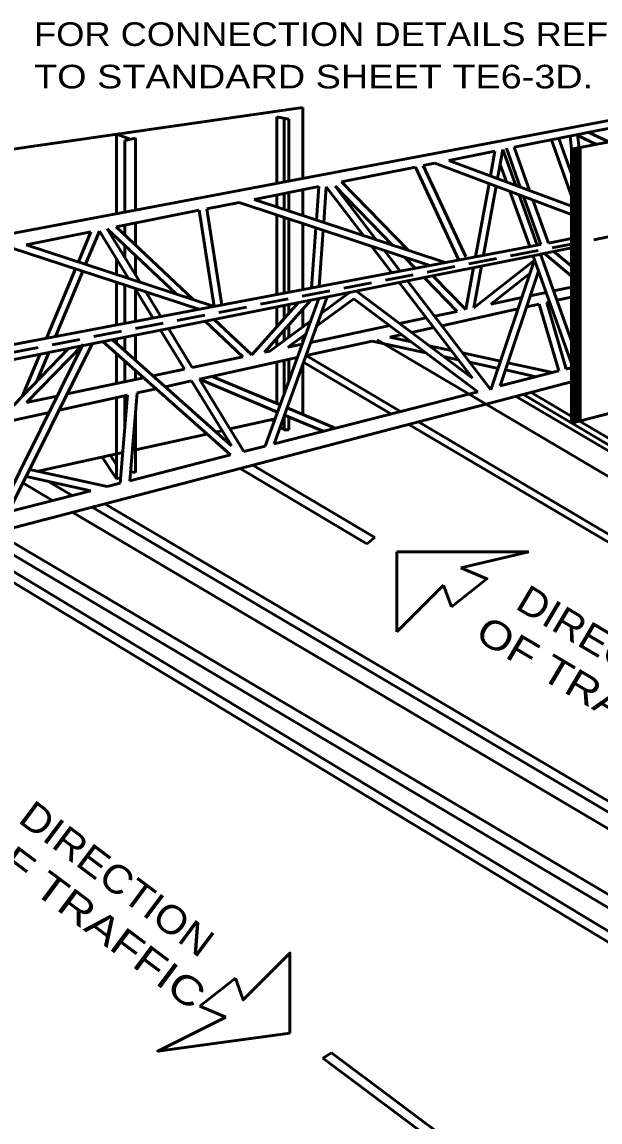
# Model space of a CAD drawing. Extents: x -111 to 744, y -77 to 467.
# Drawn here: x 499.2 to 572.7, y 204.3 to 344.2 of the extents above; entities that cross this region are included whole.
import ezdxf
from ezdxf.enums import TextEntityAlignment as Align

# ---------------------------------------------------------------- set-up
doc = ezdxf.new("R2010")
doc.units = 0
doc.header["$LTSCALE"] = 1.2
doc.linetypes.add('MEDIUM_DASHED', pattern=[4.5, 3, -1.5])
doc.layers.add('1', color=7, linetype='Continuous', lineweight=53)

msp = doc.modelspace()

# ---------------------------------------------------------------- linework, layer by layer
at = {"layer": '1'}
for p, q in [((561.783, 328.297), (612.161, 338.374)), ((569.111, 328.042), (604.991, 335.219)), ((483.311, 325.975), (534.911, 333.348)), ((534.911, 333.348), (534.911, 324.348)), ((531.611, 332.191), (531.611, 323.723)), ((531.611, 332.191), (533.111, 331.891)), ((532.511, 331.891), (532.511, 323.894)), ((533.111, 331.891), (533.111, 324.007)), ((511.211, 329.962), (512.936, 329.32)), ((511.211, 329.962), (511.211, 319.859)), ((512.261, 329.162), (513.611, 329.477)), ((512.261, 329.162), (512.261, 320.058)), ((513.611, 329.477), (513.611, 320.314)), ((566.541, 329.249), (569.111, 322.084)), ((567.493, 329.439), (569.111, 324.927)), ((569.111, 328.042), (568.92, 329.725)), ((569.709, 329.882), (572.27, 328.673)), ((570.065, 328.15), (569.865, 329.913)), ((571.288, 330.198), (573.849, 328.989)), ((553.471, 326.634), (559.354, 327.811)), ((559.354, 327.811), (558.775, 324.654)), ((560.367, 328.013), (559.688, 324.313)), ((560.367, 328.013), (562.005, 323.448)), ((560.808, 328.172), (562.579, 323.233)), ((561.783, 328.297), (563.757, 322.794)), ((569.111, 328.042), (569.111, 293.191)), ((569.399, 328.099), (569.399, 293.473)), ((569.607, 328.141), (569.607, 293.32)), ((569.815, 328.182), (569.815, 293.473)), ((570.023, 328.224), (570.023, 293.473)), ((570.191, 328.258), (570.191, 293.473)), ((550.213, 325.982), (551.683, 326.276)), ((551.683, 326.276), (569.111, 319.77)), ((553.471, 326.634), (569.111, 320.795)), ((560.022, 326.132), (560.827, 323.887)), ((569.191, 326.158), (569.191, 293.212)), ((569.503, 326.158), (569.503, 293.293)), ((539.831, 323.905), (549.244, 325.788)), ((549.244, 325.788), (554.764, 313.963)), ((550.213, 325.982), (555.634, 314.369)), ((528.697, 321.678), (536.933, 323.326)), ((536.933, 323.326), (536.631, 319.05)), ((537.891, 323.258), (537.572, 318.738)), ((537.891, 323.258), (542.624, 317.064)), ((539.02, 323.361), (544.241, 316.528)), ((539.02, 323.361), (546.368, 315.824)), ((539.831, 323.905), (548.349, 315.168)), ((558.599, 323.695), (556.888, 314.365)), ((559.512, 323.354), (557.899, 314.557)), ((531.611, 322.261), (531.611, 320.713)), ((532.511, 322.441), (532.511, 320.415)), ((533.111, 322.561), (533.111, 320.216)), ((534.911, 322.921), (534.911, 319.619)), ((561.251, 322.704), (563.775, 315.67)), ((562.429, 322.265), (564.73, 315.85)), ((563.004, 322.05), (565.196, 315.939)), ((522.675, 320.473), (526.794, 321.297)), ((522.675, 320.473), (524.59, 308.217)), ((526.794, 321.297), (551.054, 313.26)), ((528.697, 321.678), (552.996, 313.628)), ((564.181, 321.611), (566.151, 316.12)), ((511.143, 318.167), (521.733, 320.285)), ((521.733, 320.285), (523.641, 308.069)), ((531.611, 319.702), (531.611, 309.578)), ((532.511, 319.403), (532.511, 309.748)), ((533.111, 319.204), (533.111, 309.862)), ((509.037, 317.649), (507.267, 313.413)), ((509.037, 317.649), (512.735, 311.628)), ((509.988, 317.936), (514.144, 311.168)), ((509.988, 317.936), (518.788, 309.653)), ((511.143, 318.167), (520.931, 308.953)), ((512.261, 318.39), (512.261, 317.114)), ((513.611, 318.66), (513.611, 315.843)), ((534.911, 318.608), (534.911, 310.203)), ((536.561, 318.062), (536.021, 310.413)), ((537.502, 317.75), (536.996, 310.598)), ((499.71, 315.879), (507.946, 317.527)), ((507.946, 317.527), (506.351, 313.712)), ((566.151, 316.12), (569.111, 316.68)), ((450.352, 294.188), (564.73, 315.85)), ((497.792, 315.496), (521.683, 307.698)), ((499.71, 315.879), (523.641, 308.069)), ((512.261, 315.796), (512.261, 314.234)), ((543.658, 315.71), (546.229, 312.346)), ((545.276, 315.175), (547.284, 312.546)), ((564.73, 315.851), (565.196, 315.939)), ((565.141, 314.704), (569.111, 315.498)), ((566.866, 315.049), (569.111, 313.171)), ((505.078, 302.689), (565.659, 314.808)), ((511.211, 314.11), (511.211, 312.126)), ((513.611, 314.525), (513.611, 312.036)), ((547.824, 314.33), (549.208, 312.911)), ((556.675, 307.883), (564.338, 313.887)), ((564.375, 313.996), (558.828, 297.439)), ((564.216, 314.44), (569.111, 300.792)), ((565.141, 314.704), (569.111, 303.636)), ((565.659, 314.808), (569.111, 311.919)), ((505.98, 312.823), (502.304, 304.027)), ((506.896, 312.524), (503.434, 304.241)), ((556.638, 313.003), (555.66, 307.668)), ((557.651, 313.206), (556.675, 307.883)), ((558.808, 308.335), (563.784, 312.234)), ((564.898, 312.537), (560.01, 297.943)), ((511.211, 311.116), (511.211, 305.714)), ((512.261, 310.773), (512.261, 305.913)), ((547.174, 311.11), (556.493, 298.914)), ((548.222, 311.319), (558.828, 297.439)), ((550.345, 311.744), (554.548, 307.433)), ((551.467, 311.969), (555.66, 307.668)), ((513.51, 310.365), (515.83, 306.589)), ((513.611, 310.333), (513.611, 306.169)), ((514.919, 309.906), (516.839, 306.78)), ((538.022, 309.279), (531.254, 290.585)), ((540.843, 309.818), (537.267, 307.192)), ((541.714, 310.018), (556.493, 298.914)), ((563.848, 309.403), (565.869, 309.831)), ((566.817, 310.031), (569.111, 310.517)), ((567.244, 308.84), (569.111, 309.252)), ((528.424, 301.9), (534.366, 308.548)), ((530.012, 302.237), (535.934, 308.861)), ((536.922, 309.059), (530.129, 290.298)), ((531.611, 307.997), (531.611, 305.466)), ((532.511, 308.177), (532.511, 306.472)), ((533.111, 308.297), (533.111, 307.144)), ((541.411, 309.044), (536.68, 305.57)), ((541.411, 309.044), (557.159, 297.213)), ((558.808, 308.335), (562.759, 309.172)), ((563.374, 307.986), (564.998, 308.344)), ((564.998, 308.344), (567.465, 299.85)), ((565.937, 308.551), (566.299, 308.631)), ((565.937, 308.551), (568.396, 300.088)), ((534.911, 307.717), (534.911, 305.463)), ((547.22, 305.881), (550.619, 306.601)), ((551.659, 306.821), (554.548, 307.433)), ((552.587, 305.606), (562.281, 307.745)), ((517.79, 305.232), (520.824, 300.291)), ((522.486, 306.171), (527.281, 301.658)), ((523.641, 306.402), (528.424, 301.9)), ((535.876, 306.172), (530.722, 302.387)), ((533.111, 305.703), (533.111, 304.141)), ((535.926, 303.489), (545.973, 305.617)), ((548.721, 304.753), (551.554, 305.378)), ((510.67, 303.808), (525.812, 290.335)), ((511.211, 304.024), (511.211, 303.404)), ((512.261, 304.126), (512.261, 302.392)), ((513.611, 304.396), (513.611, 301.191)), ((516.786, 305.031), (519.827, 300.079)), ((531.611, 304.025), (531.611, 303.04)), ((532.511, 305.032), (532.511, 303.701)), ((535.289, 304.549), (533.001, 302.87)), ((534.911, 304.272), (534.911, 303.506)), ((535.313, 301.795), (543.724, 303.651)), ((543.724, 303.651), (550.565, 302.167)), ((544.381, 303.796), (642.104, 246.088)), ((545.969, 304.146), (547.486, 304.481)), ((545.969, 304.146), (548.727, 303.548)), ((450.362, 291.744), (505.078, 302.689)), ((496.126, 281.598), (506.843, 303.042)), ((497.433, 281.932), (508.11, 303.296)), ((498.066, 295.471), (505.078, 302.689)), ((499.751, 295.828), (506.932, 303.219)), ((509.491, 303.572), (525.687, 289.161)), ((530.012, 302.237), (530.722, 302.387)), ((533.001, 302.87), (534.82, 303.255)), ((550.973, 303.061), (553.791, 302.45)), ((569.111, 293.191), (604.991, 302.569)), ((501.441, 301.961), (499.228, 296.667)), ((502.576, 302.188), (501.054, 298.547)), ((511.211, 302.041), (511.211, 298.255)), ((512.261, 301.107), (512.261, 298.477)), ((520.824, 300.291), (527.281, 301.658)), ((521.739, 298.801), (534.203, 301.55)), ((531.611, 300.979), (531.611, 295.694)), ((532.511, 301.177), (532.511, 296.876)), ((533.111, 301.31), (533.111, 298.534)), ((534.911, 301.012), (546.124, 294.39)), ((535.337, 301.801), (547.354, 294.704)), ((552.811, 301.68), (554.691, 301.273)), ((555.239, 302.136), (560.052, 301.092)), ((556.139, 300.959), (559.745, 300.176)), ((560.996, 300.887), (566.692, 299.652)), ((513.611, 299.906), (513.611, 298.763)), ((515.815, 299.23), (519.827, 300.079)), ((534.911, 300.685), (534.911, 294.307)), ((560.01, 297.943), (567.465, 299.85)), ((560.689, 299.972), (564.614, 299.121)), ((568.396, 300.088), (569.111, 300.271)), ((450.465, 267.44), (569.111, 298.453)), ((504.925, 296.924), (514.648, 298.983)), ((517.378, 297.839), (520.747, 298.582)), ((520.747, 298.582), (525.812, 290.335)), ((521.739, 298.801), (527.391, 289.597)), ((521.739, 298.801), (531.693, 294.618)), ((523.364, 299.159), (532.021, 295.522)), ((499.751, 295.827), (503.65, 296.654)), ((503.896, 294.864), (512.608, 296.786)), ((512.608, 296.786), (511.668, 285.574)), ((512.261, 296.71), (512.261, 292.647)), ((513.835, 297.057), (512.899, 285.889)), ((513.835, 297.057), (516.221, 297.583)), ((531.254, 290.585), (557.159, 297.213)), ((562.965, 296.847), (643.866, 249.073)), ((563.952, 297.105), (644.234, 249.696)), ((511.211, 296.478), (511.211, 286.116)), ((562.057, 296.609), (643.527, 248.499)), ((488.506, 291.469), (502.615, 294.582)), ((513.611, 294.385), (513.611, 286.942)), ((532.511, 294.022), (532.511, 292.364)), ((532.58, 294.246), (537.493, 292.181)), ((532.907, 295.149), (539.033, 292.576)), ((533.111, 294.022), (533.111, 292.364)), ((534.527, 294.436), (534.911, 294.521)), ((525.627, 292.47), (531.375, 293.74)), ((531.261, 293.424), (530.993, 293.651)), ((532.511, 292.364), (532.042, 292.761)), ((548.408, 293.041), (637.3, 240.548)), ((549.63, 293.361), (635.614, 242.585)), ((513.221, 289.728), (522.696, 291.822)), ((523.853, 292.078), (524.635, 292.25)), ((532.511, 292.364), (533.111, 292.364)), ((527.391, 289.597), (530.129, 290.298)), ((501.24, 287.081), (511.994, 289.457)), ((511.211, 286.116), (509.371, 288.877)), ((511.211, 287.926), (510.422, 289.11)), ((512.899, 285.889), (525.687, 289.161)), ((500.129, 287.327), (509.992, 285.146)), ((513.611, 286.942), (512.993, 287.016)), ((526.926, 287.426), (543.042, 277.865)), ((528.558, 287.853), (544.083, 278.643)), ((499.273, 285.615), (503.068, 283.374)), ((499.687, 286.442), (507.931, 284.618)), ((502.448, 285.831), (505.538, 284.006)), ((509.992, 285.146), (511.668, 285.574)), ((511.211, 286.116), (511.726, 286.262)), ((497.433, 281.932), (507.931, 284.618)), ((509.722, 282.929), (617.424, 219.328)), ((505.632, 281.86), (615.584, 216.93)), ((508.086, 282.502), (616.534, 218.46)), ((494.032, 278.828), (611.923, 208.935)), ((495.817, 279.295), (611.923, 210.731)), ((544.083, 278.643), (543.042, 277.865)), ((490.056, 277.789), (607.956, 206.509)), ((491.676, 278.212), (608.519, 207.571)), ((546.882, 276.858), (546.882, 266.658)), ((546.882, 276.858), (563.682, 276.858)), ((563.682, 276.858), (555.021, 274.803)), ((546.882, 266.658), (552.822, 272.598)), ((552.822, 272.598), (553.804, 269.844)), ((521.816, 219.037), (526.339, 222.604)), ((525.121, 217.645), (521.816, 219.037)), ((538.568, 213.106), (537.45, 212.443)), ((538.568, 213.106), (571.377, 188.565)), ((537.45, 212.444), (570.258, 187.903))]:
    msp.add_line(p, q, dxfattribs=at)
for points in [[(431.101, 304.698), (431.997, 304.857), (612.156, 338.978)], [(555.021, 274.803), (558.326, 273.411), (553.804, 269.844)], [(533.26, 215.59), (533.26, 225.79), (527.321, 219.85), (526.339, 222.604)], [(525.121, 217.645), (516.432, 213.329), (533.26, 215.59)]]:
    msp.add_lwpolyline(points, dxfattribs=at)
at = {"layer": '1', "linetype": 'MEDIUM_DASHED'}
msp.add_lwpolyline([(450.353, 293.059), (471.201, 297.019), (573.774, 316.904)], dxfattribs=at)

# ---------------------------------------------------------------- texts
at = {"layer": '1'}
for s, width, p in [('FOR CONNECTION DETAILS REFER', 1.15, (500.701, 341.194)), ('TO STANDARD SHEET TE6-3D.', 1.2, (500.701, 335.794))]:
    msp.add_text(s, height=3, dxfattribs=dict(at, width=width)).set_placement(p)
for s, rotation, width, p in [('DIRECTION', 329.321, 1.1, (574.302, 262.269)), ('OF TRAFFIC', 329.321, 1.2, (571.241, 257.109)), ('DIRECTION', 323.204, 1.1, (510.173, 233.811)), ('OF TRAFFIC', 323.204, 1.25, (506.58, 229.006))]:
    msp.add_text(s, height=3.6, rotation=rotation, dxfattribs=dict(at, width=width)).set_placement(p, align=Align.CENTER)

doc.saveas('drawing.dxf')
